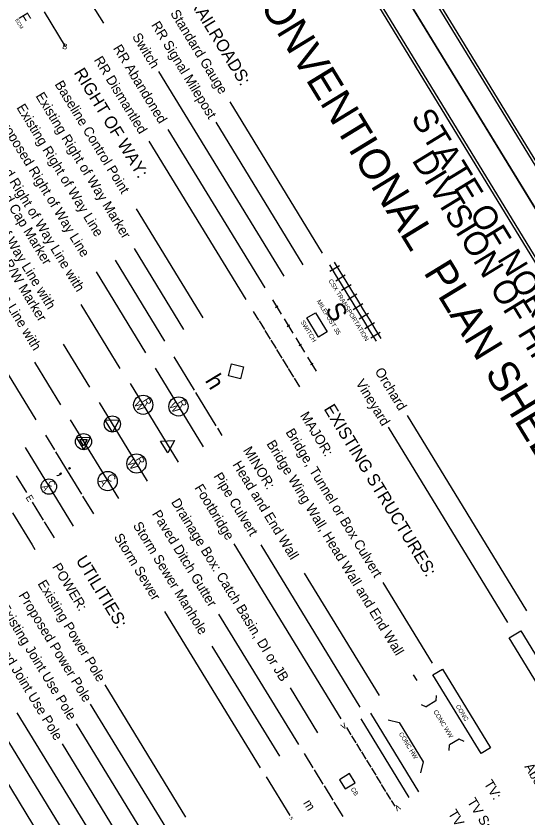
# Model space of a CAD drawing. Extents: x 1750583 to 1791140, y 783580 to 827376.
# Drawn here: x 1760850 to 1765888, y 799616 to 807509 of the extents above; entities that cross this region are included whole.
import ezdxf

# ---------------------------------------------------------------- set-up
doc = ezdxf.new("R2010")
doc.units = 0
for name, color, linetype in [('Prop Shade Heavy', 7, 'Continuous'), ('Sheet Cutting Line CELL', 7, 'Continuous'), ('Sheet Plan CELL', 7, 'Continuous'), ('Sheet Plot Border Inside CELL', 7, 'Continuous'), ('Sheet Plot Border Outside CELL', 7, 'Continuous'), ('Sheet Symbology CELL', 7, 'Continuous')]:
    doc.layers.add(name, color=color, linetype=linetype)

msp = doc.modelspace()

# ---------------------------------------------------------------- linework, layer by layer
at = {"layer": 'Prop Shade Heavy'}
msp.add_lwpolyline([(1762970.1, 804085.4), (1763088.4, 804056.9), (1763059.8, 803938.6), (1762941.5, 803967.1)], close=True, dxfattribs=at)
at = {"layer": 'Sheet Cutting Line CELL'}
for p, q in [((1770556.6, 798092), (1760908, 813883.5)), ((1770566.1, 798076.5), (1760908, 813883.5)), ((1760908, 813883.5), (1770553.7, 798096.7))]:
    msp.add_line(p, q, dxfattribs=at)
at = {"layer": 'Sheet Plan CELL'}
msp.add_lwpolyline([(1780513.6, 804401), (1771919.2, 818467.1), (1762073, 812451), (1770667.3, 798385)], close=True, dxfattribs=at)
at = {"layer": 'Sheet Plot Border Inside CELL'}
for points in [[(1761170, 813876.1), (1770715.5, 798253.4), (1780608.6, 804298.1), (1771063.2, 819920.9)], [(1750868.1, 807581.5), (1760425.8, 791938.8), (1770329.5, 797990), (1760771.8, 813632.7)]]:
    msp.add_lwpolyline(points, close=True, dxfattribs=at)
at = {"layer": 'Sheet Plot Border Outside CELL'}
for points in [[(1760908, 813883.5), (1770553.7, 798096.7), (1780822, 804370.5), (1771176.2, 820157.4)], [(1750582.8, 807574.8), (1760240.8, 791767.8), (1770566.1, 798076.5), (1760908, 813883.5)]]:
    msp.add_lwpolyline(points, close=True, dxfattribs=at)
at = {"layer": 'Sheet Symbology CELL'}
for p, q in [((1761501.9, 807778.6), (1761709.8, 807438.3)), ((1761126.5, 807549.2), (1761334.4, 807208.9)), ((1763489.8, 804947.1), (1762257.2, 806964.4)), ((1763865.2, 805176.5), (1762956.7, 806663.5)), ((1763677.5, 805061.8), (1762819.8, 806465.6)), ((1763302, 804832.4), (1762349, 806392.1)), ((1763114.3, 804717.7), (1762161.3, 806277.4)), ((1763114.3, 804717.7), (1762161.3, 806277.4)), ((1762691, 804538.2), (1762035.9, 805610.2)), ((1762503.2, 804423.5), (1762016.1, 805220.8)), ((1762315.5, 804308.8), (1761828.4, 805106)), ((1763981, 805087.5), (1764038.3, 804993.7)), ((1762127.8, 804194.1), (1761640.6, 804991.3)), ((1763934.1, 805058.9), (1763991.4, 804965)), ((1763939.3, 804997.6), (1764033.1, 805054.9)), ((1764038.3, 804993.7), (1764095.7, 804899.8)), ((1763991.4, 804965), (1764048.8, 804871.1)), ((1763996.6, 804903.7), (1764090.5, 804961.1)), ((1764048.8, 804871.1), (1764106.1, 804777.3)), ((1764054, 804809.9), (1764147.8, 804867.2)), ((1764095.7, 804899.8), (1764153, 804805.9)), ((1764106.1, 804777.3), (1764163.5, 804683.4)), ((1764111.3, 804716), (1764205.2, 804773.3)), ((1764153, 804805.9), (1764210.4, 804712.1)), ((1761875.7, 804040.1), (1761490.8, 804670)), ((1763373.1, 804716.1), (1763459.1, 804575.3)), ((1764163.5, 804683.4), (1764220.8, 804589.5)), ((1764168.7, 804622.1), (1764262.5, 804679.5)), ((1764210.4, 804712.1), (1764267.8, 804618.2)), ((1763185.4, 804601.4), (1763237, 804516.9)), ((1763427.8, 804652.9), (1763404.4, 804638.5)), ((1764220.8, 804589.5), (1764278.2, 804495.7)), ((1764267.8, 804618.2), (1764325.1, 804524.3)), ((1763487.8, 804528.4), (1763573.8, 804387.6)), ((1764226, 804528.3), (1764319.9, 804585.6)), ((1764325.1, 804524.3), (1764382.5, 804430.5)), ((1761047.6, 803534.1), (1760488.1, 804449.7)), ((1763242.7, 804507.5), (1763294.3, 804423.1)), ((1763542.5, 804465.1), (1763519.1, 804450.8)), ((1764278.2, 804495.7), (1764335.5, 804401.8)), ((1764283.4, 804434.4), (1764377.2, 804491.7)), ((1764382.5, 804430.5), (1764439.8, 804336.6)), ((1763300.1, 804413.7), (1763351.7, 804329.2)), ((1764335.5, 804401.8), (1764392.9, 804307.9)), ((1764340.7, 804340.5), (1764434.6, 804397.9)), ((1761575, 803856.3), (1761317, 804278.6)), ((1763357.4, 804319.8), (1763409, 804235.3)), ((1763602.5, 804340.6), (1763688.5, 804199.8)), ((1763657.2, 804277.4), (1763633.8, 804263.1)), ((1763414.8, 804225.9), (1763466.4, 804141.5)), ((1762402, 804155), (1762602.8, 803826.5)), ((1763472.1, 804132.1), (1763523.7, 804047.6)), ((1763717.2, 804152.9), (1763803.2, 804012.1)), ((1761291.1, 803682.9), (1761035.2, 804101.7)), ((1762218.5, 804042.9), (1762691.7, 803268.5)), ((1763529.5, 804038.2), (1763581.1, 803953.7)), ((1763772, 804089.7), (1763748.5, 804075.3)), ((1761973.3, 803893.1), (1762446.5, 803118.7)), ((1763586.8, 803944.3), (1763638.4, 803859.9)), ((1762617.1, 803803), (1762817.8, 803474.5)), ((1761668.2, 803706.7), (1762141.4, 802932.3)), ((1765877.3, 801652.8), (1764702, 803576.5)), ((1761384.3, 803533.2), (1761857.5, 802758.8)), ((1761798.4, 803493.6), (1761798.4, 803493.6)), ((1762832.2, 803451), (1762875.2, 803380.6)), ((1765689.6, 801538.1), (1764514.2, 803461.8)), ((1761139.5, 803383.6), (1761228.2, 803238.5)), ((1760939.1, 803261.2), (1761412.3, 802486.8)), ((1761514.5, 803320.1), (1761514.5, 803320.1)), ((1762342.9, 803288.1), (1762342.9, 803288.1)), ((1761239.7, 803219.7), (1761494.4, 802802.8)), ((1760851.8, 802982.1), (1760952.2, 802817.8)), ((1761505.9, 802784.1), (1761612.7, 802609.2)), ((1761009.5, 802724), (1761117.1, 802548)), ((1760815.2, 802620), (1761008.8, 802303.2)), ((1761128.5, 802529.2), (1761224.5, 802372.1)), ((1761008.8, 802303.2), (1761036.8, 802257.4)), ((1764050, 800592), (1762997.8, 802314.2)), ((1764237.8, 800706.7), (1763261.7, 802304.2)), ((1764425.5, 800821.4), (1763689.7, 802025.7)), ((1764947.1, 801140.1), (1764462.9, 801932.5)), ((1763257.5, 800107.8), (1762315.8, 801649)), ((1763633, 800337.2), (1762847.5, 801622.6)), ((1763445.2, 800222.5), (1762781.8, 801308.2)), ((1764759.4, 801025.4), (1764793.7, 800969.2)), ((1762522.6, 799622.8), (1761727.1, 800924.7)), ((1763820.7, 800451.9), (1763550, 800894.9)), ((1764984.9, 800822.2), (1764981.5, 800767.3)), ((1762334.8, 799508.1), (1761584, 800736.9)), ((1764837.3, 800732), (1764887.6, 800709.9)), ((1764981.5, 800767.3), (1764887.6, 800709.9)), ((1761771.6, 799164), (1760862.6, 800651.7)), ((1764338, 800648.1), (1764811.2, 799873.7)), ((1764244.2, 800590.7), (1764717.3, 799816.3)), ((1764513.6, 800580.7), (1764620.6, 800554.8)), ((1762147.1, 799393.4), (1761444.5, 800543.3)), ((1764103.4, 800504.7), (1764146.4, 800434.3)), ((1764620.6, 800554.8), (1764857.2, 800167.6)), ((1761583.9, 799049.3), (1760743.7, 800424.4)), ((1764152.1, 800424.9), (1764195.1, 800354.5)), ((1761959.4, 799278.7), (1761308.4, 800344.2)), ((1764200.9, 800345.1), (1764243.9, 800274.7)), ((1765113.7, 800279.6), (1765117, 800334.5)), ((1765210.9, 800391.8), (1765117, 800334.5)), ((1765261.3, 800369.8), (1765210.9, 800391.8)), ((1761396.2, 798934.5), (1760576.6, 800275.9)), ((1763686.3, 800249.9), (1763772.3, 800109.1)), ((1764249.6, 800265.3), (1764292.6, 800194.9)), ((1764298.4, 800185.5), (1764341.4, 800115.1)), ((1763783.8, 800090.3), (1763869.8, 799949.5)), ((1764347.1, 800105.8), (1764390.1, 800035.4)), ((1764857.2, 800167.6), (1764831.3, 800060.6)), ((1763310.8, 800020.5), (1763543.3, 799640.1)), ((1764395.9, 800026), (1764438.9, 799955.6)), ((1764444.6, 799946.2), (1764487.6, 799875.8)), ((1763881.3, 799930.7), (1763967.3, 799789.9)), ((1764493.4, 799866.4), (1764536.4, 799796)), ((1764542.1, 799786.6), (1764576.5, 799730.3)), ((1763978.8, 799771.1), (1764064.8, 799630.3))]:
    msp.add_line(p, q, dxfattribs=at)
for points in [[(1770233.9, 798092.7), (1761631.1, 812172.5), (1751784.8, 806156.4), (1760387.6, 792076.6)], [(1763798.2, 804589.1), (1763912.9, 804401.4), (1763827.5, 804349.2), (1763712.8, 804537)], [(1761728.8, 803531.6), (1761866, 803534.9), (1761800.5, 803414.3)], [(1761444.9, 803358.1), (1761516.6, 803240.8), (1761582.1, 803361.4)], [(1761478.1, 803340), (1761549.9, 803341.7), (1761515.6, 803278.7)], [(1762273.3, 803326.1), (1762410.5, 803329.4), (1762345, 803208.8)], [(1764033.2, 799992.1), (1764088.3, 799901.8), (1764188.1, 799962.9), (1764133, 800053.1)]]:
    msp.add_lwpolyline(points, close=True, dxfattribs=at)
for points in [[(1765817, 801456.2), (1766275.8, 800705.3), (1766163.1, 800636.5), (1765704.3, 801387.4), (1765817, 801456.2)], [(1765047.4, 801081.5), (1765520.5, 800307.1), (1765426.6, 800249.7), (1764953.5, 801024.1), (1765047.4, 801081.5)]]:
    msp.add_lwpolyline(points, dxfattribs=at)
for centre, radius in [((1762101.9, 803682.6), 94.8), ((1762448.6, 803666.3), 94.8), ((1761798.4, 803493.6), 79.2), ((1761514.5, 803320.1), 79.2), ((1762035.8, 803105), 94.8), ((1761751.9, 802931.6), 94.8), ((1761173.5, 802877.5), 75.8)]:
    msp.add_circle(centre, radius, dxfattribs=at)

# ---------------------------------------------------------------- texts
for s, height, rotation, p in [('CONVENTIONAL  PLAN SHEET SYMBOLS', 299.204, 301.42495, (1763093.3, 807871.1)), ('RAILROADS:', 121, 301.42495, (1762554.1, 807648.3)), ('F', 103.1, 301.42495, (1760870.5, 807501.4)), ('Standard Gauge', 96.25, 301.42495, (1762365.1, 807536.3)), ('ECM', 35.2, 301.42495, (1760839.1, 807470.6)), ('RR Signal Milepost', 96.25, 301.42495, (1762177.3, 807421.6)), ('Switch', 96.25, 301.42495, (1761989.6, 807306.9)), ('B', 55, 346.42505, (1761301.2, 807188.6)), ('RR Abandoned', 96.25, 301.42495, (1761801.9, 807192.2)), ('RR Dismantled', 96.25, 301.42495, (1761614.1, 807077.5)), ('RIGHT OF WAY:', 121, 301.42495, (1761415.1, 806952.3)), ('Baseline Control Point', 96.25, 301.42495, (1761227.4, 806837.6)), ('Existing Right of Way Marker', 96.25, 301.42495, (1761039.6, 806722.9)), ('Existing Right of Way Line', 96.25, 301.42495, (1760851.9, 806608.2)), ('STATE OF NORTH CAROLINA', 235.609, 301.42495, (1764731.2, 806508.8)), ('Proposed Right of Way Line', 96.25, 301.42495, (1760664.2, 806493.5)), ('Proposed Right of Way Line with', 96.25, 301.42495, (1760476.4, 806378.8)), ('Proposed Right of Way Line with', 96.25, 301.42495, (1760192.7, 806205.4)), ('  Iron Pin and Cap Marker', 96.25, 301.42495, (1760359.1, 806307.1)), ('DIVISION OF HIGHWAYS', 235.609, 301.42495, (1764739.6, 806090.6)), ('  Concrete or Granite R/W Marker', 96.25, 301.42495, (1760075.4, 806133.8)), ('Proposed Control of Access Line with', 96.25, 301.42495, (1759908.8, 806032)), ('CSX TRANSPORTATION', 44, 301.42495, (1763923, 804903.1)), ('MILEPOST 35', 44, 301.42495, (1763807.1, 804700.9)), ('S', 181.5, 301.42495, (1763887.3, 804620.8)), ('SWITCH', 44, 301.42495, (1763647.6, 804497.8)), ('Orchard', 96.25, 301.42495, (1764377.2, 804012.6)), ('h', 165, 301.42495, (1762705.8, 803921.5)), ('Vineyard', 96.25, 301.42495, (1764189.4, 803897.9)), ('W', 74.2, 301.42495, (1762006.7, 803692.1)), ('R', 74.2, 301.42495, (1762090.1, 803723.2)), ('R', 74.2, 301.42495, (1762436.9, 803706.9)), ('W', 74.2, 301.42495, (1762353.4, 803675.7)), ('EXISTING STRUCTURES:', 121, 301.42495, (1763874.9, 803642.8)), ('MAJOR:', 96.25, 301.42495, (1763642.2, 803578.2)), ('Bridge, Tunnel or Box Culvert', 96.25, 301.42495, (1763499.5, 803413.3)), ('Bridge Wing Wall, Head Wall and End Wall', 96.25, 301.42495, (1763311.7, 803298.6)), ('MINOR:', 96.25, 301.42495, (1763081.8, 803235.8)), ('R', 74.2, 301.42495, (1762024.1, 803145.6)), ('W', 74.2, 301.42495, (1761940.6, 803114.5)), ('Head and End Wall', 96.25, 301.42495, (1762977.9, 803094.6)), (';', 165, 301.42495, (1761262.7, 803023.8)), ('Pipe Culvert', 96.25, 301.42495, (1762790.3, 802980)), ('C', 59.4, 301.42495, (1761160.2, 802916.5)), ('A', 74.2, 301.42495, (1761663.7, 802929.5)), ('C', 74.2, 301.42495, (1761738.7, 802974.6)), ('A', 59.4, 301.42495, (1761102.4, 802874.3)), ('Footbridge', 96.25, 301.42495, (1762602.6, 802865.2)), ('E', 66, 301.42495, (1760942.4, 802770.6)), ('Drainage Box: Catch Basin, DI or JB', 96.25, 301.42495, (1762373.3, 802725.1)), ('Paved Ditch Gutter', 96.25, 301.42495, (1762185.4, 802610.3)), ('Storm Sewer Manhole', 96.25, 301.42495, (1761997.7, 802495.6)), ('Storm Sewer', 96.25, 301.42495, (1761810, 802380.9)), ('UTILITIES:', 121, 301.42495, (1761434.4, 802151.6)), ('POWER:', 96.25, 301.42495, (1761202.9, 802087.8)), ('Existing Power Pole', 96.25, 301.42495, (1761059.2, 801922.1)), ('Proposed Power Pole', 96.25, 301.42495, (1760871.4, 801807.4)), ('Existing Joint Use Pole', 96.25, 301.42495, (1760683.8, 801692.8)), ('Proposed Joint Use Pole', 96.25, 301.42495, (1760496, 801577.9)), ('CONC', 44, 301.42495, (1765175.8, 800716)), ('CONC WW', 44, 301.42497, (1764955.2, 800662.6)), ('v', 72.6, 31.18409, (1764068.2, 800483.4)), ('CONC HW', 44, 301.42495, (1764615.7, 800443.3)), ('Above Ground Water Line', 96.25, 301.42495, (1765848.9, 800120.7)), ('TV:', 96.25, 301.42495, (1765450.1, 799955)), ('CB', 44, 301.42495, (1764142.2, 799900.8)), ('m', 90.7, 301.42495, (1763672.8, 799763)), ('TV Satellite Dish', 96.25, 301.42495, (1765285.8, 799776.6)), ('v', 72.6, 211.6658, (1764611.5, 799751.8)), ('TV Pedestal', 96.25, 301.42495, (1765098, 799661.9)), ('S', 33, 301.42495, (1763538.4, 799616.4))]:
    msp.add_text(s, height=height, rotation=rotation, dxfattribs=at).set_placement(p)

doc.saveas('drawing.dxf')
